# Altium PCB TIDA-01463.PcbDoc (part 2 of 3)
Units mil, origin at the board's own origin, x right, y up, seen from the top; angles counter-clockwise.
Board outline 6100 x 1060 mil, 4 copper layers (Top Layer, Signal Layer 1, Signal Layer 2, Bottom Layer), stack 61.2 mil thick; 209 components, 128 nets, 660 pads, 266 vias.
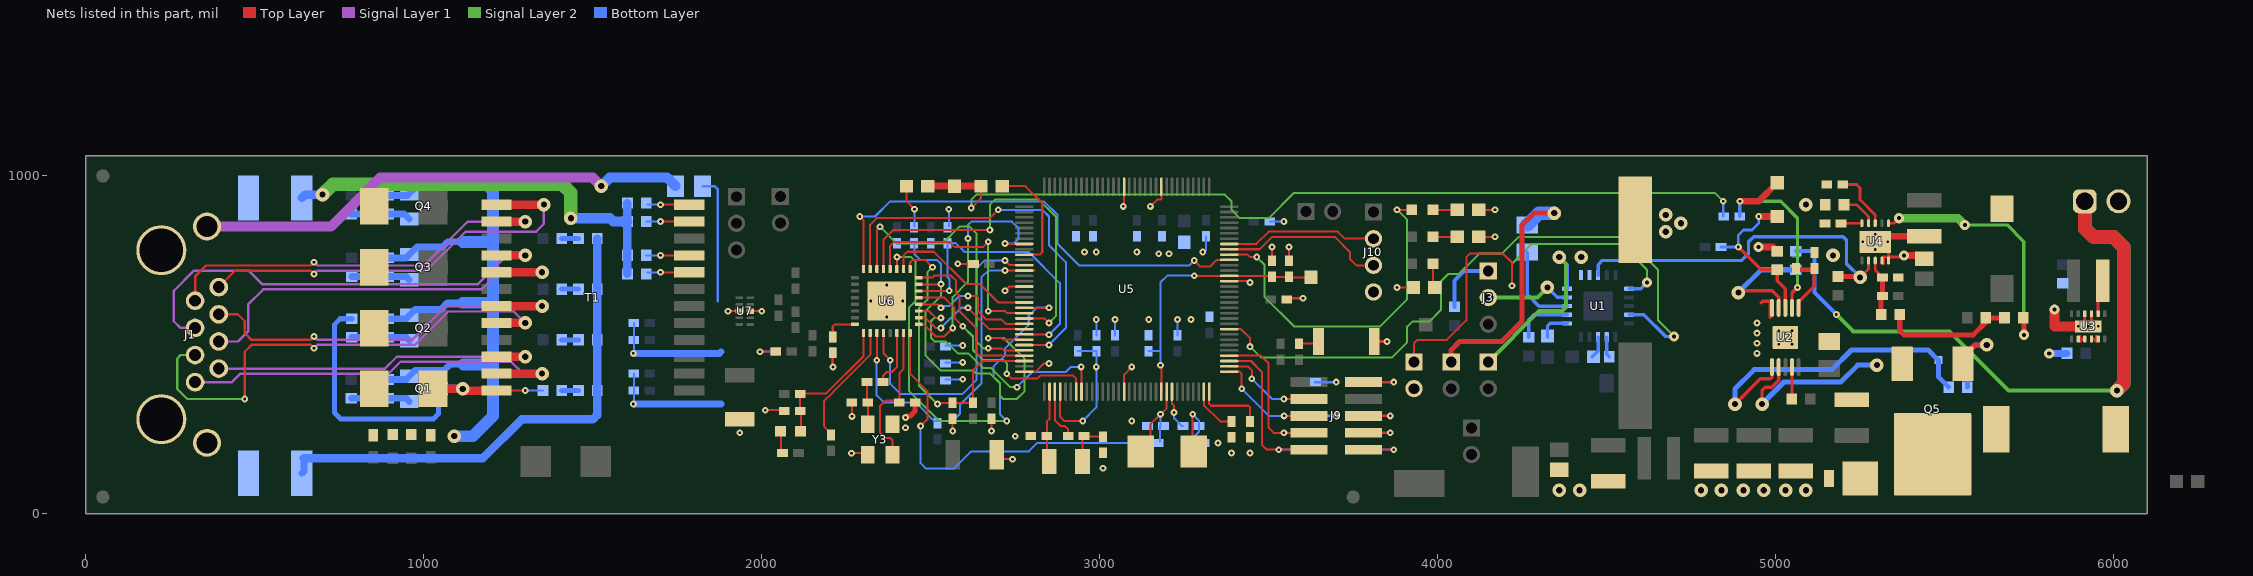
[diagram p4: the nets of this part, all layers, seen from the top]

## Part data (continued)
C57 C61: "CAP, CERM, 10 µF, 25 V, +/- 20%, X7R, AEC-Q200 Grade 1, 1210", Cap_Case=1210, Manufacturer=TDK, Supplier Part Number 1=445-5720-1-ND, TempCo=X7R, Tolerance_%=20, Value1=Unknown, Value2=25V, ValueDisplayed=10µF
C59 C63: "CAP, CERM, 1000 pF, 50 V, +/- 10%, X7R, 0402", Cap_Case=0402, Manufacturer="Wurth Elektronik", Supplier Part Number 1=732-7556-1-ND, TempCo=X7R, Tolerance_%=10, Value1=Unknown, Value2=50V, ValueDisplayed=1000pF
C60 C64: "CAP, CERM, 100 pF, 50 V, +/- 5%, C0G/NP0, 0402", Cap_Case=0402, Manufacturer="Wurth Elektronik", Supplier Part Number 1=732-7475-1-ND, TempCo=C0G/NP0, Tolerance_%=5, Value1=Unknown, Value2=50V, ValueDisplayed=100pF
C65 C66: "CAP, CERM, 12 pF, 25 V, +/- 5%, C0G/NP0, AEC-Q200 Grade 1, 0402", Cap_Case=0402, Manufacturer=Kemet, Supplier Part Number 1=399-6829-1-ND, TempCo=C0G/NP0, Tolerance_%=5, Value1=Unknown, Value2=25V, ValueDisplayed=12pF
D1 D2 D3 D4: "Diode, Schottky, 100 V, 2 A, SMB", Manufacturer="Diodes Inc.", Supplier Part Number 1=B2100-FDICT-ND, Value1=2A, Value2=0.79V
D5: "Diode, TVS, Uni, 58 V, DO-214", Manufacturer="Wurth Elektronik", Power_W=5, Supplier Part Number 1=732-9790-1-ND, Value1=5W
D6 D7 D8: "LED, Yellow, SMD", Color=yellow, Manufacturer="Wurth Elektronik", Supplier Part Number 1=732-4981-1-ND, Value1=W, Value2=2V
D9: "Diode, Schottky, 30 V, 0.1 A, SOD-323", Manufacturer="Diodes Inc.", Supplier Part Number 1=SD107WS-FDICT-ND, Value1=0.1A, Value2=0.5V
D10: "Diode, Schottky, 100 V, 2 A, DO-220AA", Manufacturer=Vishay-Semiconductor, Supplier Part Number 1=625-SS2PH10-M3, Value1=2A, Value2=0.62V
D11: "LED, Yellow, SMD", Color=Yellow, Manufacturer=Everlight, Supplier Part Number 1=19-21UYC/S530-A4/TR8CT-ND, Value1=W, Value2=2V
FID1 FID2 FID3: "Fiducial mark.  There is nothing to buy or mount.", Manufacturer=N/A
H1 H2 H3 H4 H5 H6 H7: "Bumpon, Hemisphere, 0.25 X 0.075, Clear", Manufacturer=3M, Supplier Part Number 1=SJ5382-ND
J1: "RJ-45, No LED, tab up, R/A, TH", Color=Black, Manufacturer="TE Connectivity", Supplier Part Number 1=A97716-ND
J2 J4 J5 J6 J8 J12: "Header, 2mm, 2x1, Gold, TH", Color=Black, Current_A=2.9, Manufacturer=Samtec
J3 J11: "Header, 2mm, 3x1, Gold, TH", Color=Black, Current_A=2.9, Manufacturer=Samtec
J7: "Receptacle, 2.54mm, 2x1, Tin, R/A, TH", Color=Green, Current_A=6, Manufacturer="Wurth Elektronik", Voltage_V=150
J9: "Header, 1.27mm, 5x2, Gold, Black, SMT", Color=Black, Current_A=3.3, Manufacturer=Samtec, Supplier Part Number 1=SAM8795-ND
J10: "Header, 2mm, 4x1, Gold, TH", Color=Black, Current_A=2.9, Manufacturer=Samtec
L1 L2: "Ferrite Bead, 300 ohm @ 100 MHz, 2 A, 0603", Manufacturer="Wurth Elektronik", Supplier Part Number 1=732-1592-1-ND, Value1="0.15 ohm", Value2=2A
L3: "Inductor, Shielded Drum Core, Ferrite, 3.3 µH, 1.5 A, 0.085 ohm, SMD", Manufacturer="Wurth Elektronik", Supplier Part Number 1=732-2614-1-ND, Value1="0.085 ohm", Value2=1.5A, ValueDisplayed=3.3µH
L4: "Inductor, Shielded Drum Core, Ferrite, 33 µH, 2.5 A, 0.066 ohm, SMD", Manufacturer="Wurth Elektronik", Supplier Part Number 1=732-2993-1-ND, Value1="0.066 ohm", Value2=2.5A, ValueDisplayed=33µH
L5: "Inductor, Shielded Drum Core, Ferrite, 2.2 µH, 1 A, 0.125 ohm, SMD", Manufacturer="Wurth Elektronik", Supplier Part Number 1=732-1001-1-ND, Value1="0.125 ohm", Value2=1A, ValueDisplayed=2.2µH
L6: "Inductor, Shielded Drum Core, Metal Composite, 330 µH, 0.39 A, 1.15 ohm, SMD", Manufacturer="Wurth Elektronik", Supplier Part Number 1=732-4046-1-ND, Value1="1.15 ohm", Value2=0.39A, ValueDisplayed=330µH
Logo1: library part TI_Logo, "Texas Instrument Corporate Signature"
NT1: "Single point connection between nets."
Q1 Q2 Q3 Q4: "MOSFET, N-CH, 100V, 2.7A, SSOT-3", Alternate Manufacturer=None, Manufacturer="Fairchild Semiconductor", Supplier Part Number 1=FDN8601CT-ND, Value1="? ohm", Value2="3 nC"
Q5: "MOSFET, P-CH, -100 V, 3 A, DPAK", Alternate Manufacturer=None, Manufacturer="Diodes Inc.", Supplier Part Number 1=ZXMP10A16KCT-ND, Value1="? ohm", Value2="16.5 nC"
R1 R2 R3 R4 R5 R6 R7 R8: "RES, 75.0 ohm, 1%, 0.1W, 0603", Manufacturer=Vishay-Dale, Power_W=0.1, Supplier Part Number 1=541-75.0HCT-ND, TempCo="100 ppm/C", Tolerance_%=1, Value1=1%, Value2=0.1W, Value_Code=75R0
R9 R10 R11 R12: "RES, 1.00 M, 1%, 0.1 W, 0603", Manufacturer=Vishay-Dale, Power_W=0.1, Supplier Part Number 1=541-1.00MHCT-ND, TempCo="100 ppm/C", Tolerance_%=1, Value1=1%, Value2=0.1W, Value_Code=1M00, ValueDisplayed=1.00M
R13 R14 R15 R16: "RES, 232 k, 1%, 0.1 W, 0603", Manufacturer=Vishay-Dale, Power_W=0.1, Supplier Part Number 1=541-232KHCT-ND, TempCo="100 ppm/C", Tolerance_%=1, Value1=1%, Value2=0.1W, Value_Code=232k
R17: "RES, 53.6 k, 1%, 0.1 W, 0603", Manufacturer=Vishay-Dale, Power_W=0.1, Supplier Part Number 1=541-53.6KHCT-ND, TempCo="100 ppm/C", Tolerance_%=1, Value1=1%, Value2=0.1W, Value_Code=53k6, ValueDisplayed=53.6k
R18 R19 R20 R?: "RES, 1.30 k, 1%, 0.1 W, 0603", Manufacturer="Yageo America", Power_W=0.1, Supplier Part Number 1=311-1.30KHRCT-ND, TempCo="200 ppm/C", Tolerance_%=1, Value1=1%, Value2=0.1W, Value_Code=1k30, ValueDisplayed=1.30k
R21: "RES, 27.4 k, 1%, 0.1 W, 0603", Manufacturer=Vishay-Dale, Power_W=0.1, Supplier Part Number 1=541-27.4KHCT-ND, TempCo="100 ppm/C", Tolerance_%=1, Value1=1%, Value2=0.1W, Value_Code=27k4, ValueDisplayed=27.4k
R22: "RES, 1.00 M, 1%, 0.063 W, 0402", Manufacturer=Vishay-Dale, Power_W=0.063, Supplier Part Number 1=541-1.00MLCT-ND, TempCo="100 ppm/C", Tolerance_%=1, Value1=1%, Value2=0.063W, Value_Code=1M00, ValueDisplayed=1.00M
R23: "RES, 0.18, 1%, 0.5 W, 1210", Manufacturer=Rohm, Power_W=0.5, Supplier Part Number 1=RHM.18SCT-ND, TempCo="200 ppm/C", Tolerance_%=1, Value1=1%, Value2=0.5W, Value_Code=R180, ValueDisplayed=0.18
R24: "RES, 1.3 k, 5%, 0.125 W, 0805", Manufacturer=Panasonic, Power_W=0.125, Supplier Part Number 1=P1.3KACT-ND, TempCo="200 ppm/C", Tolerance_%=5, Value1=5%, Value2=0.125W, Value_Code=1k30, ValueDisplayed=1.3k
R25: "RES, 100 k, 1%, 0.063 W, 0402", Manufacturer=Vishay-Dale, Power_W=0.063, Supplier Part Number 1=541-100KLCT-ND, TempCo="100 ppm/C", Tolerance_%=1, Value1=1%, Value2=0.063W, Value_Code=100k
R26 R31 R33: "RES, 49.9 k, 1%, 0.1 W, 0603", Manufacturer=Vishay-Dale, Power_W=0.1, Supplier Part Number 1=541-49.9KHCT-ND, TempCo="100 ppm/C", Tolerance_%=1, Value1=1%, Value2=0.1W, Value_Code=49k9, ValueDisplayed=49.9k
R27: "RES, 0, 5%, 0.1 W, 0603", Manufacturer=Vishay-Dale, Power_W=0.1, Supplier Part Number 1=541-0.0GCT-ND, TempCo="200 ppm/C", Tolerance_%=5, Value1=5%, Value2=0.1W, Value_Code=0000, ValueDisplayed=0
R28 R49 R50 R51 R59 R69: "RES, 0, 5%, 0.063 W, 0402", Manufacturer=Panasonic, Power_W=0.063, Supplier Part Number 1=P0.0JCT-ND, TempCo="600 ppm/C", Tolerance_%=5, Value1=5%, Value2=0.063W, Value_Code=0000, ValueDisplayed=0
R29: "RES, 63.4, 1%, 0.1 W, 0603", Manufacturer="Yageo America", Power_W=0.1, Supplier Part Number 1=311-63.4HRCT-ND, TempCo="200 ppm/C", Tolerance_%=1, Value1=1%, Value2=0.1W, Value_Code=63R4, ValueDisplayed=63.4
R30: "RES, 243, 1%, 0.1 W, 0603", Manufacturer="Yageo America", Power_W=0.1, Supplier Part Number 1=311-243HRCT-ND, TempCo="200 ppm/C", Tolerance_%=1, Value1=1%, Value2=0.1W, Value_Code=243R, ValueDisplayed=243
R32: "RES, 23.2 k, 1%, 0.1 W, 0603", Manufacturer=Vishay-Dale, Power_W=0.1, Supplier Part Number 1=541-23.2KHCT-ND, TempCo="100 ppm/C", Tolerance_%=1, Value1=1%, Value2=0.1W, Value_Code=23k2, ValueDisplayed=23.2k
R34 R39 R40 R41 R42 R44 R47 R60 R61 R65: "RES, 10.0 k, 1%, 0.063 W, 0402", Manufacturer=Vishay-Dale, Power_W=0.063, Supplier Part Number 1=541-10.0KLCT-ND, TempCo="100 ppm/C", Tolerance_%=1, Value1=1%, Value2=0.063W, Value_Code=10k0, ValueDisplayed=10.0k
R35: "RES, 301 k, 1%, 0.1 W, 0603", Manufacturer=Vishay-Dale, Power_W=0.1, Supplier Part Number 1=541-301KHCT-ND, TempCo="100 ppm/C", Tolerance_%=1, Value1=1%, Value2=0.1W, Value_Code=301k
R36: "RES, 105 k, 1%, 0.063 W, 0402", Manufacturer=Vishay-Dale, Power_W=0.063, Supplier Part Number 1=541-105KLCT-ND, TempCo="100 ppm/C", Tolerance_%=1, Value1=1%, Value2=0.063W, Value_Code=105k
R37: "RES, 24.9 k, 1%, 0.063 W, 0402", Manufacturer=Vishay-Dale, Power_W=0.063, Supplier Part Number 1=541-24.9KLCT-ND, TempCo="100 ppm/C", Tolerance_%=1, Value1=1%, Value2=0.063W, Value_Code=24k9, ValueDisplayed=24.9k
R38: library part CMP-0026468-1, "RES, 5.76 k, 1%, 0.063 W, 0402", Manufacturer=Vishay-Dale, Power_W=63mW, Supplier Part Number 1=541-5.76KLCT-ND, TempCo="100 ppm/C", Tolerance_%=1%, Value2=0.063W, Value_Code=5k76, ValueDisplayed=5.76k
R43 R48: "RES, 100, 1%, 0.1 W, 0402", Manufacturer=Panasonic, Power_W=0.1, Supplier Part Number 1=P100LCT-ND, TempCo="100 ppm/C", Tolerance_%=1, Value1=1%, Value2=0.1W, Value_Code=100R, ValueDisplayed=100
R45: "RES, 1.00 k, 1%, 0.1 W, 0603", Manufacturer=Vishay-Dale, Power_W=0.1, Supplier Part Number 1=541-1.00KHCT-ND, TempCo="100 ppm/C", Tolerance_%=1, Value1=1%, Value2=0.1W, Value_Code=1k00, ValueDisplayed=1.00k
R46 R52 R53 R54 R55: "RES, 49.9, 1%, 0.063 W, 0402", Manufacturer=Vishay-Dale, Power_W=0.063, Supplier Part Number 1=541-49.9LCT-ND, TempCo="100 ppm/C", Tolerance_%=1, Value1=1%, Value2=0.063W, Value_Code=49R9, ValueDisplayed=49.9
R56: "RES, 4.87 k, 1%, 0.063 W, 0402", Manufacturer=Vishay-Dale, Power_W=0.063, Supplier Part Number 1=541-4.87KLCT-ND, TempCo="100 ppm/C", Tolerance_%=1, Value1=1%, Value2=0.063W, Value_Code=4k87, ValueDisplayed=4.87k
R57: "RES, 2.21 k, 1%, 0.063 W, 0402", Manufacturer=Vishay-Dale, Power_W=0.063, Supplier Part Number 1=541-2.21KLCT-ND, TempCo="100 ppm/C", Tolerance_%=1, Value1=1%, Value2=0.063W, Value_Code=2k21, ValueDisplayed=2.21k
R58: "RES, 3.32 k, 1%, 0.063 W, 0402", Manufacturer=Vishay-Dale, Power_W=0.063, Supplier Part Number 1=541-3.32KLCT-ND, TempCo="100 ppm/C", Tolerance_%=1, Value1=1%, Value2=0.063W, Value_Code=3k32, ValueDisplayed=3.32k
R62 R63 R66 R67 R68: "RES, 2.49 k, 1%, 0.063 W, 0402", Manufacturer=Vishay-Dale, Power_W=0.063, Supplier Part Number 1=541-2.49KLCT-ND, TempCo="100 ppm/C", Tolerance_%=1, Value1=1%, Value2=0.063W, Value_Code=2k49, ValueDisplayed=2.49k
R64: "RES, 332, 1%, 0.063 W, 0402", Manufacturer=Vishay-Dale, Power_W=0.063, Supplier Part Number 1=541-332LCT-ND, TempCo="100 ppm/C", Tolerance_%=1, Value1=1%, Value2=0.063W, Value_Code=332R, ValueDisplayed=332
S1: "Switch, Push Button, SMD", CurrentRating_mA=50, Manufacturer=Alps, Supplier Part Number 1=688-SKRKAE
SH-J1 SH-J2 SH-J3 SH-J4 SH-J5 SH-J6 SH-J7 SH-J8: "Shunt, 2mm, Gold plated, Black", Manufacturer=Samtec, Supplier Part Number 1=2SN-BK-G-ND
T1: "Transformer, 350 uH, SMT", Manufacturer="Wurth Elektronik"
TP1 TP2: library part 5019, "Test Point, Miniature, SMT", Manufacturer=Keystone, Supplier Part Number 1=36-5019TR-ND
TP3 TP4 TP5 TP6 TP7: library part PAD_1MM_SQUARE, "1.0x1.0mm pad, square, SMD", Manufacturer=Any
U1: library part CMP-0013753-2, "Mid Power bt PoE PD Interface with Automatic Maintain Power Signature, Advanced Startup and Ultra-Low Standby Power, RGW0020B (VQFN-20)", Alternate Manufacturer="Texas Instruments", Alternate PartNumber=TPS2372-4RGWT
U2: "PFET Buck Controller for High Power LED Drives, 10-pin eMSOP, Pb-Free", Manufacturer="Texas Instruments", PackageTopMarking=ZXTT*SYHB, PowerWise=Y, Supplier Part Number 1=LM3409HVMYX-ND
U3: "360nA IQ Step Down Converter for Low Power Applications, DSS0012A (WSON-12)", Alternate Manufacturer="Texas Instruments", Alternate PartNumber=TPS62740DSST
U4: "3V-65V, 150mA Synchronous Buck Converter With Ultra-Low IQ, DRC0010J (VSON-10)", Alternate Manufacturer="Texas Instruments", Alternate PartNumber=LM5165DRCT
U5: "Tiva C Series Microcontroller, PDT0128A", Alternate Manufacturer="Texas Instruments", Alternate PartNumber=TM4C1292NCPDTI3
U6: library part CMP-0076010-2, "Robust, Low Power 10/100 Ethernet Physical Layer Transceiver, RHB0032B (VQFN-32)", Alternate Manufacturer="Texas Instruments", Alternate PartNumber=DP83822IRHBT
U7: "1, 4, 6 CHANNEL PROTECTION SOLUTION FOR SUPER-SPEED (UP TO 6 GBPS) INTERFACE, DQA0010A", Alternate Manufacturer="Texas Instruments"
Y1: "CRYSTAL, 32.768KHZ, 9PF, SMD", Frequency=32.768kHz, Frequency Stability=±20ppm, Manufacturer="Abracon Corporation", Supplier Part Number 1=535-9544-1-ND
Y2: "Crystal, 25MHz,  SMD", Frequency=25MHz, Frequency Stability=±30ppm, Manufacturer=NDK, Supplier Part Number 1=644-1274-1-ND
Y3: "Crystal, 25MHz, 8pF, SMD", Frequency=25MHz, Frequency Stability=±50ppm, Manufacturer=Kyocera, Supplier Part Number 1=1253-1142-1-ND

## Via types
v1: diameter 20, hole 8, Top Layer to Bottom Layer, 184 vias
v2: diameter 40, hole 18, Top Layer to Bottom Layer, 50 vias
v3: diameter 19.68, hole 7.87, Top Layer to Bottom Layer, 21 vias
v4: diameter 30, hole 12, Top Layer to Bottom Layer, 11 vias

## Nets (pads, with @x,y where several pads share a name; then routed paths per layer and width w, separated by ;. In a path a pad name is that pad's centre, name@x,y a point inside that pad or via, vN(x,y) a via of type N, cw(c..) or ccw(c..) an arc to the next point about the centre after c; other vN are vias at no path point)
ANA_DIM: C50.1 R28.1 R45.2 TP4.1 | length 2620.7
  Top Layer w6: v1(2620,905) 2648.5,933.5 R45.2@2648.5,970
  Top Layer w20: C50.1@2491.5,970 TP4.1@2570,970 R45.2@2648.5,970
  Signal Layer 2 w6: v1(2620,905) 2620,930 2635,945 3370,945 3390,925 3390,900 3415,875 3500,875 3575,950 4820,950 v1(4845,925)
  Bottom Layer w6: R28.1@4845,881.38 R28.1@4846.38,880
  Bottom Layer w8: R28.1@4845,881.38 v1(4845,925)
AUTCLS: J2.1 U1.10 | length 557.5
  Signal Layer 2 w12: J2.1@4150,449.37 4300.63,600 4368.46,600 4380,611.54 4380,740 v2(4360,760)
  Bottom Layer w10: v2(4360,760) 4383.46,736.54 U1.10@4383.46,666.18
BR+: C11.1 D1.1 D2.1 D3.1 D4.1 L1.1
BR-: C11.2 C13.2 C14.2 C15.2 C16.2 L2.1 Q1.2 Q2.2 Q3.2 Q4.2 R13.1 R14.1 R15.1 R16.1 | length 2342.5
  Bottom Layer w20: R13.1@840,397.56 946.85,397.56 Q1.2@956.69,407.4 974.29,425 1060,425 1077.5,442.5 1117.5,442.5 ; R16.1@840,942.56 C16.2@895,942.56 Q4.2@951.85,942.56 ; R14.1@841.69,577.56 946.85,577.56 Q2.2@956.69,587.4 974.29,605 1050.5,605 1070.5,625 1115,625 ; R15.1@841.69,757.56 946.85,757.56 Q3.2@956.69,767.4 979.29,790 1055.5,790 1070.5,805 1115,805 ; Q4.2@956.69,947.4 974.29,965 1055,965 1075,985 1115,985
  Bottom Layer w35: v2(1090,230) 1145,230 1205,290 1205,442.5 ; 1115,625 1205,625 ; 1115,805 1205,805 ; 1115,985 1175,985 1205,955 1205,805 ; 1117.5,442.5 1205,442.5 ; 1205,442.5 1205,625 ; 1205,625 1205,805
BSVG: C5.1 C10.2 J1.9 J1.10 J1.11 J1.12 NT1.1 | length 1478
  Signal Layer 1 w30: J1.10@357.95,850.47 725.47,850.47 870,995 1500,995 v2(1525,970)
  Bottom Layer w30: v2(1525,970) 1550,995 1720,995 NT1.1@1745,970
BT: U1.19 U5.105 | length 1961.5
  Top Layer w6: U5.105@3383.15,546.89 3418.11,546.89 3445,520 v1(3445,495)
  Signal Layer 2 w6: v1(3445,495) 3477.71,462.29 3864.58,462.29 3910,507.7 3910,554.06 3925.94,570 3976.33,570 4010,603.67 4010,688.11 4031.89,710 4062.93,710 4122.93,770 4190,770 4240,820 4555,820 4652.1,722.9 4652.1,572.9 v4(4700,525)
  Bottom Layer w10: U1.19@4566.54,589.41 4610.59,589.41 4675,525 v4(4700,525)
BT_LED: D8.2 U5.119 | length 1024.5
  Top Layer w6: U5.119@3383.15,767.36 3437.64,767.36 3445,760 v1(3465,760) ; v1(3880,900) D8.2@3923.5,900
  Signal Layer 2 w6: v1(3465,760) 3488.35,736.65 3488.35,641.65 3575,555 3830,555 3910,635 3910,870 v1(3880,900)
EPHY_CLKOUT: R50.1 U6.24 | length 1108.6
  Top Layer w6: U6.24@2438.9,535.51 2438.9,414.45 2490,363.35 2490,280 v1(2470,260)
  Bottom Layer w6: v1(2470,260) 2470,150 2485,135 2570,135 2620,185 2790,185 2815,210 R50.1@3126.38,210
EPHY_COL: U5.71 U6.29 | length 670.2
  Top Layer w6: U6.29@2464.49,639.84 2540.16,639.84 2570,610 2570,580 v1(2595,555) ; v1(2725,415) 2740,400 2815,400 2825,410 2920,410 2930.39,399.61 U5.71@2930.39,361.85
  Signal Layer 2 w6: v1(2595,555) 2625,525 2625,485 2655,455 2715.26,455 2725,445.26 v1(2725,415)
EPHY_CRS: U5.72 U6.27 | length 760.1
  Top Layer w6: U6.27@2464.49,600.47 2494.53,600.47 2515,580 v1(2530,580) ; v1(2945,435) 2946.14,433.86 U5.72@2946.14,361.85
  Signal Layer 2 w6: v1(2530,580) 2510,580 2500.77,570.77 2500.77,520.88 2511.65,510 2545,510 2580,475 2611.55,475 2655,431.55 2678.45,431.55 2735,375 v1(2755,375)
  Bottom Layer w6: v1(2755,375) 2800,420 2899.93,420 2914.93,435 v1(2945,435)
EPHY_INTRN: U5.118 U6.8 | length 1424.4
  Top Layer w6: v1(2290,880) 2301.1,868.9 U6.8@2301.1,724.49 ; v1@3281.61,751.61 v1(3280,750) 3297.83,732.17 3327.17,732.17 3346.61,751.61 U5.118@3383.15,751.61
  Bottom Layer w6: v1(2290,880) 2335,880 2380,925 2835,925 2875,885 2875,799.82 2939.82,735 3265,735 v1(3280,750)
EPHY_LED_0: D11.1 R66.1 R68.2 U6.17 | length 416.5
  Top Layer w6: R68.2@2113.62,306.81 2113.62,356.81 2191.21,356.81 2301.57,467.18 U6.17@2301.57,540.47 ; D11.1@2115.91,245 R68.2@2115.91,304.53
EPHY_MDC: U5.44 U6.20 | length 930.9
  Top Layer w6: U6.20@2360.16,535.51 2360.16,474.84 v1(2380,455) ; v1(2720,750) 2734.13,735.87 U5.44@2776.85,735.87
  Bottom Layer w6: v1(2380,455) 2380,385 2410.79,354.21 2593.24,354.21 2635,395.97 2635,725 2660,750 v1(2720,750)
EPHY_MDIO: R57.2 U5.45 U6.19 | length 1066.5
  Top Layer w6: v1@2340.47,455.47 U6.19@2340.47,535.51 ; v1(2720,720) 2806.99,720
  Bottom Layer w6: v1(2340,455) 2340,350.87 2360.87,330 2455,330 2510.47,274.53 2520,274.53 2564.53,274.53 2586.65,296.65 2586.65,322.64 2650,385.98 2650,700 2670,720 v1(2720,720)
EPHY_RXCK: U5.40 U6.25 | length 745.4
  Top Layer w6: U6.25@2464.49,561.1 2478.9,561.1 2515,525 2540,525 v1(2565,550) ; v1(2720,800) 2721.14,798.86 U5.40@2776.85,798.86
  Signal Layer 2 w6: v1(2565,550) 2565,641.56 2610,686.56 v1(2610,815)
  Bottom Layer w6: v1(2610,815) 2610,855 2620,865 2740,865 2760,845 2760,815 2745,800 v1(2720,800)
EPHY_RXD0: R65.1 R67.2 U5.57 U6.30 | length 901.4
  Top Layer w6: U6.30@2464.49,659.53 2554.53,659.53 v1(2555,660) ; U5.57@2776.85,531.14 2848.86,531.14 v1(2850,530)
  Bottom Layer w6: R65.1@2503.62,803.19 R67.2@2550,803.19 ; v1(2555,660) 2555,695 2550,700 R67.2@2550,801.38 2573.62,801.38 2600,775 2790,775 2881.91,683.09 2881.91,561.91 v1(2850,530)
EPHY_RXD1: R60.1 R62.2 U5.58 U6.31 | length 1245.8
  Top Layer w6: U6.31@2464.49,679.21 v1@2529.69,679.21 ; v1(2670,520) 2710,520 2714.61,515.39 U5.58@2776.85,515.39
  Signal Layer 2 w6: v1(2530.47,680) 2530.47,645.94 2484.21,599.68 2484.21,469.13 2528.35,425 2625,425 2635,415 2676.26,415 2705,386.26 2705,350 2715,340 2755,340 2776.85,361.85 2776.85,459.99 2716.84,520 v1(2670,520)
  Bottom Layer w6: R60.1@2403.66,801.34 R62.2@2451.81,801.34 ; R62.2@2451.81,803.19 R62.2@2451.81,801.34 ; v1@2528.62,686.02 v1@2530.47,684.17 ; v1(2530.47,680) v1@2530.47,684.17 ; R62.2@2451.81,801.34 2451.81,768.62 2468.62,751.81 2518.19,751.81 2530.47,739.53 v1@2530.47,684.17
EPHY_RXD2: U5.61 U6.32 | length 503.8
  Top Layer w6: U6.32@2464.49,698.9 2503.9,698.9 2510,705 2560,705 2575,690 2575,655 2585,645 2585,600 2635,550 2635,475 2641.85,468.15 U5.61@2776.85,468.15
EPHY_RXD3: R61.1 R63.2 U5.62 U6.1 | length 908.3
  Top Layer w6: U6.1@2438.9,724.49 2438.9,743.9 2446.81,751.81 2483.19,751.81 v1(2505,730) ; v1(2520,325) 2523.62,328.62 R63.2@2565,328.62 R61.1@2625,328.62 2625,425 2652.4,452.4 U5.62@2776.85,452.4
  Signal Layer 2 w6: v1(2505,730) 2490,715 2490,633.62 2465,608.62 2465,380 v1(2520,325)
EPHY_RXDV: U5.56 U6.26 | length 376.1
  Top Layer w6: U6.26@2464.49,580.79 2484.21,580.79 2515,550 v1(2530,550) ; v1(2610,610) 2673.11,546.89 U5.56@2776.85,546.89
  Bottom Layer w6: v1(2530,550) 2590,610 v1(2610,610)
EPHY_RXER: U5.55 U6.28 | length 388.6
  Top Layer w6: U6.28@2464.49,620.16 2464.65,620 2520,620 v1(2530,610) ; v1(2610,645) 2635,645 2640,640 2640,600 2665,575 2710,575 2722.36,562.64 U5.55@2776.85,562.64
  Bottom Layer w6: v1(2530,610) 2535,615 2555,615 2585,645 v1(2610,645)
EPHY_TXCK: U5.51 U6.2 | length 464.4
  Top Layer w6: U6.2@2419.21,724.49 2419.21,764.21 2430.79,775.79 2509.21,775.79 2604.22,680.78 2644.22,680.78 2699.37,625.63 U5.51@2776.85,625.63
EPHY_TXD0: U5.53 U6.4 | length 690.4
  Top Layer w6: U6.4@2379.84,724.49 2379.84,793.03 2391.81,805 2555,805 2570,790 2655,790 v1(2670,805) ; v1(2670,600) 2720,600 2725.87,594.13 U5.53@2776.85,594.13
  Signal Layer 2 w6: v1(2670,600) v1(2670,805)
EPHY_TXD1: U5.54 U6.5 | length 1112.1
  Top Layer w6: U6.5@2360.16,724.49 2360.16,810.75 2389.41,840 v1(2675,840) ; U5.54@2776.85,578.39 2836.61,578.39 v1(2850,565)
  Signal Layer 2 w6: v1(2675,840) 2675,915 2690,930 2820,930 2870,880 2870,585 v1(2850,565)
EPHY_TXD2: U5.60 U6.6 | length 936.8
  Top Layer w6: U6.6@2340.47,724.49 2340.47,840.47 v1(2350,850) ; v1(2670,490) 2710,490 2716.1,483.9 U5.60@2776.85,483.9
  Signal Layer 2 w6: v1(2350,850) 2400,800 2534.84,800 2584.84,850 2615,850 2635,830 2635,531.56 2636,530.56 2636,509 2655,490 v1(2670,490)
EPHY_TXD3: U5.59 U6.7 | length 1181.3
  Top Layer w6: U6.7@2320.79,724.49 2320.79,855.79 2340,875 2675,875 v1(2700,900) ; U5.59@2776.85,499.65 v1@2849.65,499.65
  Bottom Layer w6: v1(2700,900) 2830,900 2850,880 2850,795 2900,745 2900,550 v1(2850,500)
EPHY_TXEN: U5.52 U6.3 | length 1327.3
  Top Layer w6: U6.3@2399.53,724.49 v1@2399.53,759.53 ; U5.52@2776.85,609.88 2849.88,609.88 v1(2850,610)
  Signal Layer 2 w6: v1(2400,760) 2441.69,760 2455,746.69 2455,630 2435,610 2435,365 2525,275 v1(2725,275)
  Bottom Layer w6: v1(2725,275) 2705,295 2705,386.26 2685,406.26 2685,435 2720,470 2720,490 2790,560 2790,586.52 2813.48,610 v1(2850,610)
GND: C1.2 C2.2 C3.2 C4.2 C17.2 C18.2 C19.2 C20.2 C21.2 C22.2 C23.2 C26.2 C27.2 C28.2 C29.2 C31.2 C33.2 C34.2 C35.2 C36.2 C37.2 C38.2 C39.2 C40.2 C41.2 C42.2 C43.2 C44.2 C45.2 C46.2 C47.2 C48.2 C49.2 C50.2 C51.2 C52.2 C53.2 C54.2 C55.2 C56.2 C57.2 C58.2 C59.2 C60.2 C61.2 C62.2 C63.2 C64.2 C65.2 C66.2 D10.2 J4.2 J7.2 J9.3 J9.5 J9.9 J10.4 NT1.2 R18.1 R19.1 R20.1 R25.1 R26.1 R36.1 R37.1 R38.1 R39.2 R40.2 R44.1 R56.2 R62.1 R63.1 R67.1 R68.1 S1.1 U1.11 U1.12 U2.5 U2.11 U3.3 U3.4 U3.8 U3.9 U3.10 U3.11 U3.13@5925,555 U4.9 U4.10 U4.11 U5.10 U5.17 U5.48 U5.64 U5.80 U5.114 U6.33@2370,630 U7.3@1933.56,600 U7.8@1966.44,600 Y3.2 Y3.4 | length 4281.3
  Top Layer w6: v1(1900,600) U7.3@1933.56,600 ; U7.8@1966.44,600 v1(2000,600) ; U7.8@1966.91,604.96 U7.8@1967.72,604.15 ; v1(1995,480) C64.2@2041.38,480 ; v1(2010,306.81) R68.1@2066.38,306.81 ; v1(2210.47,434.96) R56.2@2210.47,481.34 ; v1(2265.75,179.68) Y3.2@2314.06,179.68 ; v1(2266.85,288.58) C66.2@2266.85,334.96 ; C50.2@2428.5,970 2428.5,925.12 v1(2451.81,901.81) ; v1(2565,245) R63.1@2565,281.38 ; v1(2580,740) C44.2@2626.38,740 ; v1(2680,245) C43.2@2680,281.38 ; C57.2@2696.81,161.85 v1(2741.85,161.85) ; v1(2720,660) 2732.87,672.87 U5.48@2776.85,672.87 ; U5.64@2776.85,420.91 2810.91,420.91 2835,445 v1(2850,445) ; v1(3070,910) 3072.13,912.13 U5.17@3072.13,968.15 ; U5.80@3072.13,361.85 3072.13,412.13 v1(3095,435) ; v1(3150,910) 3170,930 3180,930 3182.36,932.36 U5.10@3182.36,968.15 ; U5.114@3383.15,688.62 3441.38,688.62 v1(3445,685) ; C47.2@3510,748.62 v1(3510,790) ; C42.2@3555.47,638.15 v1(3601.85,638.15) ; C48.2@3560,748.62 v1(3560,790) ; v1(3880,670) R18.1@3932.44,670 ; R19.1@4117.56,820 v1(4170,820) ; R20.1@4117.56,900 v1(4170,900)
  Top Layer w8: J9.3@3780.12,240 v1(3860,240) ; J9.5@3780.12,290 v1(3860,290) ; J9.9@3780.12,390 v1(3870,390) ; S1.1@3812.67,510 v1(3850,510) ; U4.11@5295,805 5300,805 5335,770 5335,765 5340,760 ; U4.9@5314.69,749.88 5314.69,748.32 5315,748 5315,743.98 5316.02,743.98 5320,740 5320,760 5340,760 ; v4@5375,760 5340,760 ; U3.8@5895.47,517.6 5901.14,523.26 ; 5901.14,525.47 5901.14,523.26 ; 5909.01,517.6 5901.14,509.72 5901.14,523.26 ; U3.4@5915.16,592.4 5915.16,564.84 v3(5925,555) 5934.84,564.84 U3.3@5934.84,592.4 ; 5940.99,517.6 5948.86,509.72 5948.86,525.47 5954.53,519.81 U3.11@5954.53,517.6
  Top Layer w10: 4958.13,625 4962.33,629.19 4984.08,629.19 4984.08,582.17 4989.63,587.72 U2.5@4989.63,609.6
  Top Layer w12: U4.11@5292.44,802.44 U4.11@5295,805
  Top Layer w15: v1(2425,285) 2430,290 2440,290 2453.62,303.62 C65.2@2453.62,330
  Top Layer w20: v4(4950,790) 4992.56,790 R26.1@5005,777.56 ; U4.11@5295,805 5311.85,821.85 C31.2@5440,821.85 ; v4(5380,765) 5429.53,765 C27.2@5440,754.53
  Top Layer w30: v4(5825,605) 5825,555 v3(5925,555)
  Bottom Layer w6: v1@1621.38,326.38 C2.2@1621.38,365 C1.2@1621.38,415 ; v1@1621.38,476.38 C4.2@1621.38,515 C3.2@1621.38,565 ; v1(1995,480) C62.2@2041.38,480 ; v1@2210,435.43 C63.2@2210,476.38 ; R62.1@2451.81,850.43 v1(2451.81,901.81) ; C59.2@2543.62,398.35 v1(2595,398.35) ; C60.2@2543.62,448.35 v1(2595,448.35) ; C58.2@2543.62,498.35 v1(2595,498.35) ; R67.1@2553.62,850.43 v1(2553.62,901.81) ; C51.2@2990,528.62 v1(2990,575) ; C39.2@3045,528.62 v1(3045,575) ; C40.2@3230,528.62 v1(3230,575) ; 3315,780 C46.2@3315,821.38 ; C45.2@3503.62,865 v1(3545,865)
  Bottom Layer w8: NT1.2@1825,970 1860,970 1870,960 1870,630 ; R44.1@3638.62,290 v1(3700,290) ; C54.2@3638.62,390 v1(3700,390)
  Bottom Layer w20: v1(1620,325) 1879.88,325 ; v1(1620,475) 1875,475 1880,480 ; v4(5810,475) C28.2@5862.44,475
  other v1: 3010,135 3390,180 3445,180 3350,210 2750,230 1935,240 2425,255 3095,275 4945,475 4945,505 4945,535 4945,565 3145,575 3270,575 3175,770 3205,770 2955,775 2990,775 3110,775 3305,775
  other v2: 4360,70 4420,70 4780,70 4840,70 4905,70 4965,70 5030,70 5090,70 4425,760 5170,765 4675,835 4720,860 4675,885 5090,915
  other v3: 5009.31,502.32 5048.68,502.32 5009.31,541.68 5048.68,541.68 5895.47,555 5954.53,555 2370,582.76 2322.76,630 2370,630 2417.24,630 2370,677.24 5295,782.36 5257.6,805 5332.4,805 5295,827.64
I2C5SCL: J10.2 U5.121 | length 450.4
  Top Layer w6: U5.121@3383.15,798.86 3463.86,798.86 3500,835 3705,835 3725.63,814.37 J10.2@3810,814.37
I2C5SDA: J10.3 U5.120 | length 488.8
  Top Layer w6: U5.120@3383.15,783.11 3473.11,783.11 3510,820 3695,820 3740,775 3740,755 3759.37,735.63 J10.3@3810,735.63
IRSHDL_EN: J4.1 U1.16 | length 1264.6
  Top Layer w6: J4.1@3930,449.37 3930,505 3940,515 4027.24,515 4085,572.76 4085,760 4095.44,770.44 4193.42,770.44 4220,743.86 v1(4220,675)
  Signal Layer 2 w6: v1(4220,675) 4220,740 4278.97,798.97 4542.87,798.97 4620,721.84 v4(4620,685)
  Bottom Layer w10: U1.16@4566.54,666.18 4601.18,666.18 v4(4620,685)
LED_PWM0: R45.1 U5.42 | length 340.5
  Top Layer w6: R45.1@2711.5,970 2780,970 2830,920 2830,775 2822.36,767.36 U5.42@2776.85,767.36
MPS_DUTY: J3.2 U1.9 | length 258.1
  Signal Layer 2 w12: J3.2@4150,640 4295,640 v2(4325,670)
  Bottom Layer w10: v2(4325,670) 4354.41,640.59 U1.9@4383.46,640.59
NetC5_2: C5.2 R1.1 R2.1 R3.1 R4.1 | length 1279.8
  Signal Layer 2 w40: v2(700,945) 730,975 1410,975 1435,950 v2(1435,875)
  Bottom Layer w25: C5.2@638.74,935 648.74,945 v2(700,945) ; R1.1@1602.44,710 R2.1@1602.44,765 R3.1@1602.44,865 R4.1@1602.44,920
  Bottom Layer w30: v2(1435,875) 1550,875 1560,865 R3.1@1602.44,865
NetC6_2: C6.2 R5.2 | length 49.9
  Bottom Layer w15: C6.2@1407.56,365 R5.2@1457.44,365
NetC7_2: C7.2 R6.2 | length 49.9
  Bottom Layer w15: C7.2@1407.56,515 R6.2@1457.44,515
NetC8_2: C8.2 R7.2 | length 49.9
  Bottom Layer w15: C8.2@1407.56,665 R7.2@1457.44,665
NetC9_2: C9.2 R8.2 | length 49.9
  Bottom Layer w15: C9.2@1407.56,815 R8.2@1457.44,815
NetC10_1: C10.1 R5.1 R6.1 R7.1 R8.1 | length 1490.5
  Bottom Layer w20: C10.1@638.74,120 645,126.26 C10.1@645,165
  Bottom Layer w25: C10.1@645,165 683.74,165 1175,165 1289.96,279.96 1500,279.96 1512.56,292.52 R5.1@1512.56,365 R6.1@1512.56,515 R7.1@1512.56,665 R8.1@1512.56,815
NetC13_1: C13.1 Q1.1 R9.1 R13.2 | length 175.8
  Bottom Layer w20: R9.1@785,342.44 C13.1@895,342.44 946.85,342.44 Q1.1@956.69,332.6
NetC14_1: C14.1 Q2.1 R10.1 R14.2 | length 174.1
  Bottom Layer w20: R10.1@786.69,522.44 C14.1@895,522.44 946.85,522.44 Q2.1@956.69,512.6
NetC15_1: C15.1 Q3.1 R11.1 R15.2 | length 174.1
  Bottom Layer w20: R11.1@786.69,702.44 C15.1@895,702.44 946.85,702.44 Q3.1@956.69,692.6
NetC16_1: C16.1 Q4.1 R12.1 R16.2 | length 177.8
  Bottom Layer w20: R12.1@785,887.44 C16.1@895,887.44 941.85,887.44 Q4.1@956.69,872.6
NetC25_2: C25.2 U2.9 | length 94.8
  Top Layer w10: C25.2@5047.44,340 5048.66,341.22 U2.9@5048.66,434.29
NetC26_1: C26.1 R32.2 U2.4 | length 372.3
  Top Layer w10: v2(4890,655) 4895,660 4990,660 5009.29,640.71 U2.4@5009.29,595.71
  Bottom Layer w15: v2(4890,655) 4957.44,722.44 R32.2@5060,722.44
NetC30_2: C30.2 C32.1 R35.2 | length 390.6
  Top Layer w15: C32.1@5367.56,590 5367.56,542.44 5380,530 5585,530 5622.56,567.56 C30.2@5622.56,580 R35.2@5677.44,580
NetC32_2: C32.2 R34.1 R38.2 U4.8 | length 170.4
  Top Layer w8: U4.8@5295,749.88 5295,721.38 R38.2@5316.38,700
  Top Layer w15: C32.2@5312.44,590 5312.44,641.06 R34.1@5316.38,645 R38.2@5316.38,700
NetC33_1: C33.1 U4.4 | length 107
  Top Layer w8: C33.1@5202.56,915 5240,915 5275.31,879.68 U4.4@5275.31,860.12
NetC47_1: C47.1 C48.1 C49.1 TP3.1 U5.87 U5.115 | length 813.1
  Top Layer w6: v1(3180,440) 3182.36,437.64 U5.87@3182.36,361.85 ; v1(3280,705) 3280.63,704.37 U5.115@3383.15,704.37 3507.01,704.37 C47.1@3510,701.38 C48.1@3560,701.38 3561.38,700 TP3.1@3625,700
  Bottom Layer w6: C49.1@3145,481.38 3178.62,481.38 ; v1(3180,440) 3180,685 3200,705 v1(3280,705)
NetC51_1: C51.1 R46.2 U5.68 | length 424.7
  Top Layer w6: U5.68@2883.15,361.85 2883.15,286.85 2895,275 v1(2950,275)
  Bottom Layer w6: R46.2@2935,481.38 C51.1@2990,481.38 v1(2990,435) 2990,315 v1(2950,275)
NetC52_1: C52.1 R49.2 Y1.1 | length 132.9
  Top Layer w6: Y1.1@2949.21,155 2949.21,225.59 R49.2@2953.62,230 ; R49.2@2954.21,229.41 2955,228.62 C52.1@3010,228.62
NetC53_1: C53.1 U5.66 Y1.2 | length 213.1
  Top Layer w6: Y1.2@2850.79,155 2843.62,162.17 C53.1@2843.62,230 2843.62,273.62 2851.65,281.65 U5.66@2851.65,361.85
NetC55_1: C55.1 R50.2 U5.88 Y2.1 | length 287.3
  Top Layer w6: Y2.1@3121.26,185 3150,213.74 3150,265 v1(3180,295) 3198.11,313.11 U5.88@3198.11,361.85
  Bottom Layer w6: R50.2@3177.99,214.37 C55.1@3177.99,260 ; C55.1@3180,262.01 v1(3180,295)
NetC56_1: C56.1 R51.1 Y2.2 | length 212.3
  Top Layer w6: Y2.2@3275,188.74 v1(3275,295)
  Bottom Layer w6: C56.1@3261.38,210 3293.62,242.24 R51.1@3293.62,260 3293.62,276.38 v1(3275,295)
NetC65_1: C65.1 U6.23 Y3.3 | length 437.6
  Top Layer w6: Y3.3@2386.89,179.68 2386.89,218.54 2380.47,224.96 2365.47,224.96 2350.47,239.96 2350.47,319.96 2365.47,334.96 2406.85,334.96 2406.85,416.34 2419.69,429.17 U6.23@2419.69,540.47
NetC66_1: C66.1 R59.2 Y3.1 | length 119.2
  Top Layer w6: R59.2@2311.38,390 2311.38,332.24 C66.1@2313.62,330 ; Y3.1@2314.06,270.24 C66.1@2314.06,328.54
NetD6_1: D6.1 R18.2 | length 68.9
  Top Layer w6: R18.2@3986.5,671.06 D6.1@3986.5,740
NetD7_1: D7.1 R19.2 | length 75.9
  Top Layer w6: D7.1@3986.5,820 R19.2@4062.44,820
NetD8_1: D8.1 R20.2 | length 75.9
  Top Layer w6: D8.1@3986.5,900 R20.2@4062.44,900
NetD9_1: D9.1 R27.1 U2.6 | length 971.8
  Top Layer w10: v2(4880,325) 4955,400 4985,400 4989.61,404.61 U2.6@4989.61,434.29
  Bottom Layer w15: v2(4880,325) 4880,370 4936.69,426.69 5166.69,426.69 5225,485 5451.69,485 D9.1@5481.69,455 5481.69,405.75 R27.1@5512.44,375
NetD9_2: D9.2 Q5.1 R27.2 | length 279
  Top Layer w15: Q5.1@5554.76,438.86 5554.76,464.76 5590,500 v2(5625,500)
  Bottom Layer w15: R27.2@5568.31,375.75 D9.2@5568.31,455 5568.31,478.31 5590,500 v2(5625,500)
NetD10_1: D10.1 L4.1 Q5.4
NetD11_2: D11.2 R64.2 | length 55.9
  Top Layer w6: R64.2@2056.85,189.11 D11.2@2056.85,245
NetJ1_1: J1.1 T1.23 | length 1201.5
  Top Layer w25: T1.23@1214.96,415 v2(1350,415)
  Signal Layer 1 w7: J1.1@322.91,389.84 431.84,389.84 457,415 896,415 931,450 1258,450 1293,415 v2(1350,415)
NetJ1_2: J1.2 T1.22 | length 1006.5
  Top Layer w25: T1.22@1214.96,465 v2(1300,465)
  Signal Layer 1 w7: J1.2@392.99,430 885,430 920,465 v2(1300,465)
NetJ1_3: J1.3 T1.20 | length 1486.2
  Top Layer w7: v1(470,340) 470,480 490,500 665,500 v1(675,490)
  Top Layer w25: T1.20@1214.96,565 v2(1300,565)
  Signal Layer 1 w7: v1(675,490) 685,500 973,500 1072,599 1266,599 v2(1300,565)
  Signal Layer 2 w7: J1.3@322.91,470.16 280.16,470.16 270,460 270,370 300,340 v1(470,340)
NetJ1_4: J1.4 T1.17 | length 1223.7
  Top Layer w25: T1.17@1214.96,715 v2(1350,715)
  Signal Layer 1 w7: J1.4@392.99,510.32 450.32,510.32 480,540 480,620 525,665 1171,665 1221,715 v2(1350,715)
NetJ1_5: J1.5 T1.16 | length 1362.7
  Top Layer w25: T1.16@1214.96,765 v2(1300,765)
  Signal Layer 1 w7: J1.5@322.91,550.47 279.53,550.47 260,570 260,660 320,720 481,720 521,680 1160,680 1245,765 v2(1300,765)
NetJ1_6: J1.6 T1.19 | length 1193.6
  Top Layer w7: J1.6@392.99,590.63 449.37,590.63 470,570 470,535 490,515 665,515 v1(675,525)
  Top Layer w25: T1.19@1214.96,615 v2(1350,615)
  Signal Layer 1 w7: v1(675,525) 685,515 965,515 1065,615 v2(1350,615)
NetJ1_7: J1.7 T1.14 | length 1209.7
  Top Layer w7: J1.7@322.91,630.79 322.91,702.91 355,735 665,735 v1(675,745)
  Top Layer w25: T1.14@1214.96,865 v2(1300,865)
  Signal Layer 1 w7: v1(675,745) 685,735 1000,735 1130,865 v2(1300,865)
NetJ1_8: J1.8 T1.13 | length 1244.9
  Top Layer w7: J1.8@392.99,670.94 442.05,720 665,720 v1(675,710)
  Top Layer w25: T1.13@1214.96,915 v2(1355,915)
  Signal Layer 1 w7: v1(675,710) 685,720 1008,720 1123,835 1332.09,835 1355,857.91 v2(1355,915)
NetJ3_1: J3.1 R17.1 | length 189.3
  Bottom Layer w12: R17.1@4050,612.56 4050,690 4078.74,718.74 J3.1@4150,718.74
NetJ6_1: J6.1 R24.1 | length 769.8
  Top Layer w15: J6.1@4040,449.37 4040,485 4065,510 4190,510 4250,570 4250,855 4285,890 v2(4345,890)
  Bottom Layer w40: R24.1@4265,855 4300,890 v2(4345,890)
NetJ7_1: J7.1 L4.2 R32.1 | length 3125.7
  Top Layer w40: J7.1@5915,920 5915,845 5940,820 6000,820 6030,790 6030,385 v2(6010,365)
  Signal Layer 2 w12: v1(5180,590) 5230,540 5515,540 5690,365 v2(6010,365)
  Signal Layer 2 w40: J7.1@5915,920 5915,845 5940,820 6000,820 6030,790 6030,385 v2(6010,365)
  Bottom Layer w12: R32.1@5060,777.56 5106.14,777.56 5115,768.7 5115,655 v1(5180,590)
  Bottom Layer w40: J7.1@5915,920 5915,845 5940,820 6000,820 6030,790 6030,385 v2(6010,365)
NetJ9_1: J9.1 R43.1 | length 156.3
  Top Layer w6: J9.1@3780.12,190 v1(3870,190)
  Bottom Layer w6: R43.1@3803.62,190 v1(3870,190)
NetJ9_2: J9.2 R41.1 U5.99 | length 532.7
  Top Layer w6: U5.99@3383.15,452.4 3447.6,452.4 3480,420 3480,205 3495,190 v1(3530,190) J9.2@3619.88,190
  Bottom Layer w6: v1(3530,190) R41.1@3591.38,190
NetJ9_4: J9.4 R42.1 U5.100 | length 488.9
  Top Layer w6: U5.100@3383.15,468.15 3476.85,468.15 3500,445 3500,255 3515,240 v1(3545,240) J9.4@3619.88,240
  Bottom Layer w6: v1(3545,240) R42.1@3591.38,240
NetJ9_6: J9.6 R44.2 U5.97 | length 363
  Top Layer w6: U5.97@3383.15,420.91 3414.09,420.91 3420,415 v1(3420,370) ; v1(3545.69,290) J9.6@3619.88,290
  Bottom Layer w6: v1(3420,370) 3500,290 v1(3545.69,290) R44.2@3591.38,290
NetJ9_8: J9.8 U5.98 | length 291.4
  Top Layer w6: U5.98@3383.15,436.65 3438.35,436.65 3450,425 v1(3450,400) ; v1(3545,340) J9.8@3619.88,340
  Bottom Layer w6: v1(3450,400) 3510,340 v1(3545,340)
NetL5_1: L5.1 U3.2 | length 83.8
  Top Layer w8: U3.2@5954.53,592.4 L5.1@5954.53,676.22
NetL6_1: L6.1 R35.1 U4.1 | length 761.8
  Top Layer w8: U4.1@5334.37,860.12 5350.12,860.12 v4(5365,875)
  Top Layer w15: R35.1@5732.56,580 5735,577.56 v4(5735,530)
  Signal Layer 2 w10: v4(5560,855) 5685,855 5735,805 v4(5735,530)
  Signal Layer 2 w25: v4(5365,875) 5540,875 v4(5560,855)
NetQ5_3: Q5.3 R23.1 U2.7 | length 528.8
  Top Layer w10: v2(4960,325) 4960,365.35 4969.65,375 4989,375 5009.31,395.32 U2.7@5009.31,434.4
  Bottom Layer w15: v2(4960,325) 5025,390 5192.98,390 5242.98,440 v2(5300,440)
NetR1_2: R1.2 T1.8 | length 122.5
  Top Layer w6: v1(1700,715) T1.8@1785.04,715
  Bottom Layer w6: R1.2@1662.56,715 v1(1700,715)
NetR2_2: R2.2 T1.9 | length 127.5
  Top Layer w6: v1(1700,765) T1.9@1785.04,765
  Bottom Layer w6: R2.2@1657.56,765 v1(1700,765)
NetR3_2: R3.2 T1.11 | length 127.5
  Top Layer w6: v1(1700,865) T1.11@1785.04,865
  Bottom Layer w6: R3.2@1657.56,865 v1(1700,865)
NetR4_2: R4.2 T1.12 | length 122.5
  Top Layer w6: v1(1700,915) T1.12@1785.04,915
  Bottom Layer w6: R4.2@1662.56,915 v1(1700,915)
NetR21_1: R21.1 U1.2 | length 61.3
  Bottom Layer w10: U1.2@4500.59,523.46 4500.59,471.85 R21.1@4507.44,465
NetR22_1: R22.1 R25.2 U2.1 | length 201.1
  Top Layer w10: U2.1@5068.35,595.71 5068.35,627.36 5115,674.02 R25.2@5115,722.44
  Top Layer w12: R22.1@5060,722.44 R25.2@5115,722.44
NetR24_2: R24.2 U1.8 | length 258
  Bottom Layer w10: R24.2@4265,775 4265,650 4300,615 U1.8@4383.46,615
NetR26_2: R26.2 R69.2 TP7.1 U2.3 | length 501.6
  Top Layer w10: v1(4890,790) 4957.56,722.44 R26.2@5005,722.44 5005,690 5029,666 U2.3@5029,609.6
  Top Layer w20: v1(4950,880) TP7.1@5005,880
  Bottom Layer w8: R69.2@4838.62,790 v1(4890,790) 4890,825 4905,840 4930,840 4950,860 v1(4950,880)
NetR28_2: R28.2 TP6.1 U2.2 | length 641.2
  Top Layer w10: U2.2@5048.69,609.6 5048.69,653.69 v1(5065,670)
  Top Layer w20: v1(4895,925) 4950,925 TP6.1@5005,980
  Signal Layer 2 w10: v1(4895,925) 5015,925 5065,875 v1(5065,670)
  Bottom Layer w10: R28.2@4893.62,880 4893.62,923.62 v1(4895,925)
NetR29_2: R29.2 U1.3 | length 65.7
  Bottom Layer w10: R29.2@4457.56,465 4475,482.44 U1.3@4475,523.46
NetR30_2: R30.2 U1.6 | length 94.6
  Bottom Layer w10: R30.2@4325,522.56 4325,555 4333.82,563.82 U1.6@4383.46,563.82
NetR31_1: R31.1 U1.7 | length 171.9
  Bottom Layer w10: R31.1@4270,522.56 4270,575 4284.41,589.41 U1.7@4383.46,589.41
NetR36_2: R36.2 U4.5 | length 61.9
  Top Layer w8: R36.2@5193.74,860.12 U4.5@5255.63,860.12
NetR37_2: R37.2 U4.3 | length 179
  Top Layer w8: R37.2@5198.62,975 5240,975 5250,965 5250,930 5295,885 U4.3@5295,860.12
NetR39_1: R39.1 U5.95 | length 141.7
  Top Layer w6: U5.95@3308.35,361.85 3308.35,321.65 3356.38,273.62 R39.1@3390,273.62
NetR40_1: R40.1 U5.96 | length 202.7
  Top Layer w6: U5.96@3324.09,361.85 3324.09,325.91 3330,320 3440,320 3445,315 R40.1@3445,273.62
NetR48_1: R48.1 S1.2 | length 50.9
  Top Layer w6: R48.1@3590,503.63 S1.2@3640.94,503.63
NetR49_1: R49.1 U5.67 | length 154.8
  Top Layer w6: U5.67@2867.4,361.85 2867.4,277.6 2885,260 2896.65,260 2906.38,250.28 R49.1@2906.38,230
NetR51_2: R51.2 U5.89 | length 117.6
  Top Layer w6: U5.89@3213.86,361.85 3213.86,326.14 3220,320 v1(3220,300)
  Bottom Layer w6: v1(3220,300) 3220,282.44 3242.44,260 R51.2@3246.38,260
NetR56_1: R56.1 U6.16 | length 99.4
  Top Layer w6: R56.1@2210,523.62 2210,555 2216.1,561.1 U6.16@2275.51,561.1
NetR58_1: R58.1 U6.18 | length 374.6
  Top Layer w6: R58.1@2209.57,233.62 2183.62,259.57 2183.62,333.11 2209.47,358.96 2209.47,359.52 2321.26,471.3 U6.18@2321.26,540.47
NetR59_1: R59.1 U6.22 | length 177
  Top Layer w6: R59.1@2358.62,390 2358.62,409.12 2369.42,419.92 2385.43,419.92 2400,434.49 U6.22@2400,540.47
PG: R33.1 U1.13 U4.7 | length 1077.8
  Top Layer w8: v2(5250,700) 5275.31,725.32 U4.7@5275.31,749.88
  Top Layer w15: R33.1@5185,702.56 5247.44,702.56 v2(5250,700)
  Bottom Layer w10: U1.13@4475,706.54 4475,737.58 4487.42,750 4900,750 4920,770 4920,805 4935,820 5200,820 5210,810 5210,740 v2(5250,700)
PR12: C6.1 D1.2 Q1.3 R10.2 T1.24 | length 1114.1
  Top Layer w6: T1.24@1214.96,365 v1(1300,365)
  Top Layer w25: D1.2@1027.01,370 v2(1115,370) 1120,365 T1.24@1214.96,365
  Bottom Layer w6: v1(1300,365) C6.1@1352.44,365
  Bottom Layer w15: R10.2@786.69,577.56 752.56,577.56 735,560 735,300 753.58,281.42 1028.58,281.42 1043.31,296.15 Q1.3@1043.31,370
  Bottom Layer w25: Q1.3@1043.31,370 v2(1115,370)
